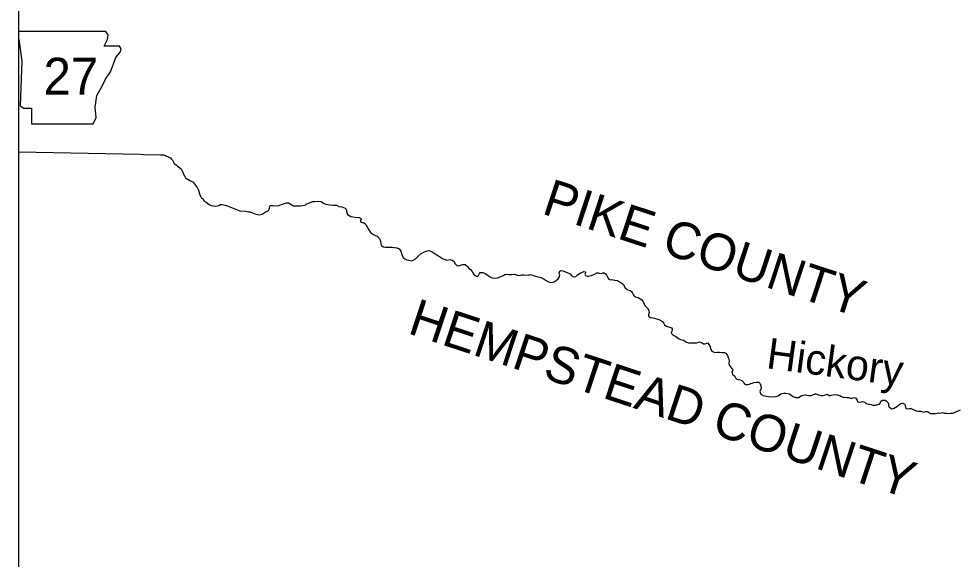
# Model space of a CAD drawing. Extents: x 79818 to 83933, y 50884 to 53307.
# Drawn here: x 80798.6 to 81014.4, y 52954.9 to 53079 of the extents above; entities that cross this region are included whole.
import ezdxf

# ---------------------------------------------------------------- set-up
doc = ezdxf.new("R2010")
doc.units = 0
for name, color, linetype in [('Level 2', 7, 'Continuous'), ('Level 21', 7, 'Continuous'), ('Level 30', 7, 'Continuous'), ('Level 9', 7, 'Continuous'), ('R_No Plot', 7, 'Continuous')]:
    doc.layers.add(name, color=color, linetype=linetype)

msp = doc.modelspace()

# ---------------------------------------------------------------- linework, layer by layer
at = {"layer": 'Level 2'}
for points in [[(80798.6, 53048.45), (80826.43, 53047.86), (80827.31, 53047.81), (80831.14, 53047.74)], [(80831.14, 53047.74), (80831.58, 53047.74), (80831.84, 53047.72), (80832.25, 53047.59), (80832.52, 53047.44), (80832.88, 53047.27), (80833.16, 53047.16), (80833.4, 53047.01), (80833.59, 53046.84), (80833.84, 53046.55), (80834.15, 53045.9), (80834.29, 53045.76), (80834.68, 53045.41), (80835.04, 53045.1), (80835.56, 53044.78), (80835.85, 53044.52), (80836.22, 53043.72), (80836.39, 53043.33), (80836.67, 53042.75), (80836.86, 53042.48), (80837.3, 53042.16), (80837.58, 53042.06), (80837.83, 53041.86), (80838.58, 53041.43), (80839.09, 53040.85), (80839.51, 53040.21), (80839.83, 53039.6), (80840.06, 53038.79), (80840.23, 53038.4), (80840.51, 53037.83), (80840.8, 53037.74), (80841.07, 53037.2), (80841.62, 53036.85), (80842.27, 53036.37), (80842.78, 53036.09), (80843.78, 53035.95), (80844.47, 53036.14), (80844.85, 53036.32), (80845.18, 53036.35), (80845.99, 53036.19), (80846.39, 53036.05), (80847.79, 53035.49), (80849.32, 53034.88), (80850.51, 53034.8), (80850.9, 53034.74), (80851.28, 53034.68), (80851.58, 53034.67), (80852.06, 53034.52), (80852.78, 53034.16), (80853.77, 53033.98), (80854.43, 53034.15), (80855.15, 53034.55), (80855.61, 53034.78), (80855.92, 53034.96), (80856.03, 53035.23), (80856.11, 53035.48), (80856.18, 53035.96), (80856.38, 53036.14), (80856.86, 53036.13), (80857.88, 53036.07), (80858.49, 53036.17), (80859.3, 53036.5), (80860.07, 53036.69), (80860.52, 53036.71), (80860.84, 53036.51), (80861.61, 53036.04), (80863.13, 53036), (80864.31, 53036.2), (80864.55, 53036.41), (80865.46, 53036.79), (80866.1, 53037), (80866.51, 53037.03), (80867.41, 53037.11), (80867.99, 53037.03), (80868.5, 53036.66), (80869.09, 53036.39), (80870, 53036.27), (80870.85, 53036.21), (80871.47, 53036.17), (80872.07, 53035.91), (80872.71, 53035.81), (80873.48, 53035.49), (80873.69, 53035.3), (80873.83, 53034.75), (80874.03, 53034.07), (80874.77, 53033.59), (80875.81, 53033.47), (80876.7, 53033.33), (80877, 53033.2), (80877.17, 53033.08), (80877.23, 53032.92), (80877.01, 53032.77), (80877.02, 53032.44), (80877.27, 53032.28), (80877.5, 53032.23), (80877.67, 53032.22), (80877.98, 53031.98), (80878.2, 53031.77)], [(80878.2, 53031.77), (80878.89, 53030.49), (80879.31, 53029.94), (80880, 53029.49), (80880.44, 53029.26), (80880.88, 53029.05), (80881, 53028.93), (80881.37, 53028.57), (80881.61, 53027.96), (80881.71, 53027.34), (80881.79, 53027.01), (80882.2, 53026.64), (80882.78, 53026.54), (80883.47, 53026.57), (80884.31, 53026.55), (80885.34, 53026.43), (80885.87, 53026.2), (80886.3, 53025.66), (80886.48, 53024.83), (80886.81, 53024.19), (80887.2, 53023.85), (80887.64, 53023.64), (80888.79, 53023.38), (80889.63, 53023.85), (80890.28, 53024.48), (80890.94, 53025.09), (80891.68, 53025.51), (80892.1, 53025.6), (80892.7, 53025.75), (80893.45, 53025.5), (80894.12, 53025.05), (80894.95, 53024.53), (80895.37, 53024.25), (80895.59, 53024.09), (80895.81, 53023.95), (80896.85, 53023.6), (80897.53, 53023.68), (80898.08, 53023.58), (80898.51, 53023.25), (80898.64, 53022.78), (80899.21, 53022.25), (80899.78, 53022.37), (80900.41, 53022.6), (80901.06, 53022.55), (80901.58, 53022.1), (80901.89, 53021.66), (80902.28, 53021.4), (80902.61, 53020.94), (80902.81, 53020.66), (80903.04, 53020.31), (80903.32, 53020.07), (80903.61, 53019.91), (80903.89, 53019.9), (80904.11, 53020.06), (80904.25, 53020.37), (80904.29, 53020.53), (80904.49, 53020.74), (80905.05, 53020.71), (80905.61, 53020.54), (80906.01, 53020.28), (80906.57, 53019.93), (80906.77, 53019.77), (80907.2, 53019.5), (80907.81, 53019.4), (80908.42, 53019.48), (80909.08, 53019.72), (80909.75, 53020.06), (80910.13, 53020.27), (80910.53, 53020.35), (80911.15, 53020.27), (80911.67, 53020.29), (80912.36, 53020.34), (80913.02, 53020.16), (80913.51, 53020.07), (80914, 53020.19), (80914.42, 53020.17), (80915.48, 53020.16), (80915.95, 53020.24), (80916.54, 53020.09), (80916.9, 53019.98), (80918, 53019.7), (80918.47, 53019.6), (80919.13, 53019.22), (80919.59, 53018.89), (80920.18, 53018.56), (80920.77, 53018.45), (80921.47, 53018.61), (80921.91, 53018.87), (80922.35, 53019.3), (80922.66, 53019.73), (80922.71, 53019.99), (80922.72, 53020.22), (80922.66, 53020.43), (80922.62, 53020.53), (80922.58, 53020.69), (80922.74, 53021.06), (80923.06, 53021.2), (80923.48, 53021.12), (80924.02, 53020.92), (80924.59, 53020.65), (80925.09, 53020.41)], [(80925.09, 53020.41), (80925.33, 53020.15), (80925.59, 53019.91), (80925.74, 53019.79), (80926.14, 53019.71), (80926.43, 53019.85), (80926.83, 53020.22), (80927.39, 53020.59), (80927.93, 53020.83), (80928.3, 53020.97), (80928.61, 53020.86), (80928.61, 53020.69), (80928.54, 53020.5), (80928.5, 53020.39), (80928.66, 53020.02), (80929.02, 53019.9), (80929.31, 53019.87), (80929.67, 53019.95), (80930.03, 53020.05), (80930.73, 53020.32), (80931.22, 53020.63), (80931.53, 53020.63), (80931.78, 53020.57), (80932.23, 53020.53), (80932.59, 53020.63), (80932.93, 53020.64), (80933.23, 53020.42), (80933.46, 53020.14), (80933.88, 53019.46), (80934, 53019.18), (80934.41, 53019.06), (80934.62, 53019.1), (80935.41, 53018.99), (80935.97, 53018.89), (80936.43, 53018.63), (80936.73, 53018.46), (80937.01, 53018.26), (80937.36, 53017.95), (80937.64, 53017.33), (80938.02, 53017.01), (80938.32, 53016.78), (80938.91, 53016.61), (80939.18, 53016.38), (80939.35, 53016.12), (80939.57, 53015.7), (80939.85, 53015.34), (80940.09, 53015.14), (80940.42, 53015.06), (80940.74, 53014.98), (80941.54, 53014.44), (80941.95, 53013.82), (80942.25, 53013.14), (80942.91, 53012.54), (80943.16, 53012.04), (80943.22, 53011.56), (80943.09, 53011.09), (80943.07, 53010.7), (80943.58, 53010.37), (80944.17, 53010.33), (80944.74, 53010.17), (80945.5, 53009.92), (80946.06, 53009.64), (80946.3, 53009.48), (80946.53, 53009.18), (80946.61, 53009.02), (80946.77, 53008.73), (80947.2, 53008.44), (80947.68, 53008.23), (80948.12, 53008.13), (80948.38, 53008.01), (80948.55, 53007.77), (80948.54, 53007.48), (80948.31, 53006.85), (80948.74, 53006.33), (80949.37, 53006.01), (80949.97, 53005.6), (80950.48, 53005.33), (80950.78, 53005.25), (80951.13, 53005.2), (80951.58, 53004.89), (80951.84, 53004.76), (80952.32, 53004.62), (80952.89, 53004.6), (80953.5, 53004.6), (80953.6, 53004.61), (80954.17, 53004.61), (80954.57, 53004.73), (80954.8, 53004.81), (80955.24, 53004.7), (80955.52, 53004.49), (80955.68, 53004.38), (80956.09, 53004.33), (80956.47, 53004.53), (80956.69, 53004.56), (80956.96, 53004.24), (80957.17, 53003.87), (80957.38, 53003.09), (80957.64, 53002.68), (80958.32, 53002.41), (80958.94, 53002.47), (80959.42, 53002.45)], [(80959.42, 53002.45), (80959.94, 53002.36), (80960.23, 53002.36), (80960.53, 53002.35), (80960.87, 53002.22), (80961.07, 53001.88), (80961.22, 53001.67), (80961.38, 53001.26), (80961.45, 53001.06), (80961.58, 53000.47), (80961.57, 52999.89), (80961.71, 52999.36), (80962.13, 52998.8), (80962.4, 52998.64), (80962.46, 52998.29), (80962.2, 52998.01), (80962.35, 52997.28), (80962.62, 52997.14), (80962.79, 52997.04), (80963.01, 52996.72), (80963.07, 52996.54), (80963.38, 52996.28), (80963.79, 52996.15), (80964.13, 52996.09), (80964.53, 52995.96), (80964.77, 52995.72), (80964.98, 52995.49), (80965.08, 52995.24), (80965.42, 52995.01), (80965.88, 52995), (80966.25, 52995.11), (80966.62, 52995.26), (80966.86, 52995.36), (80967.24, 52995.5), (80967.78, 52995.57), (80968.17, 52995.58), (80968.45, 52995.54), (80968.68, 52995.33), (80968.73, 52995.22), (80968.85, 52994.81), (80968.87, 52994.61), (80968.93, 52994.37), (80968.95, 52994.09), (80968.8, 52993.78), (80968.67, 52993.4), (80968.78, 52992.94), (80968.88, 52992.79), (80969.38, 52992.48), (80970.15, 52992.34), (80970.58, 52992.25), (80971.46, 52992.22), (80972.25, 52992.25), (80972.86, 52992.46), (80973.5, 52992.89), (80974.18, 52993.06), (80974.59, 52993.04), (80975.47, 52992.86), (80975.95, 52992.54), (80976.33, 52992.29), (80976.85, 52992.07), (80977.49, 52992.02), (80978.31, 52992.53), (80979.01, 52992.69), (80979.17, 52992.67), (80979.9, 52992.51), (80980.41, 52992.52), (80981.33, 52992.86), (80981.49, 52992.91), (80981.9, 52992.75), (80982.14, 52992.67), (80982.74, 52992.53), (80983.22, 52992.5), (80983.72, 52992.65), (80984.04, 52992.78), (80984.34, 52992.68), (80984.6, 52992.54), (80984.85, 52992.5), (80985.06, 52992.6), (80985.73, 52992.71), (80986.49, 52992.63), (80986.72, 52992.58), (80987.01, 52992.48), (80987.4, 52992.28), (80987.68, 52992.1), (80988.01, 52992.15), (80988.71, 52992.07), (80989.05, 52992.02), (80989.47, 52991.91), (80989.87, 52991.91), (80990.21, 52992.02), (80990.67, 52991.86), (80990.84, 52991.65), (80990.96, 52991.42), (80991.1, 52991.08), (80991.4, 52990.98), (80991.9, 52991.08), (80992.2, 52991.13), (80992.74, 52991.01), (80993.06, 52990.69), (80993.62, 52990.53), (80993.84, 52990.51)], [(80993.84, 52990.51), (80994.2, 52990.42), (80994.55, 52990.31), (80994.78, 52990.26), (80995.11, 52990.28), (80995.27, 52990.3), (80995.75, 52990.42), (80996.12, 52990.51), (80996.32, 52990.85), (80996.32, 52991.01), (80996.42, 52991.22), (80996.79, 52991.41), (80997.03, 52991.44), (80997.39, 52991.41), (80997.71, 52991.24), (80998.11, 52990.86), (80998.19, 52990.61), (80998.21, 52990.24), (80998.26, 52989.98), (80998.86, 52989.44), (80999.36, 52989.5), (81000.25, 52990.09), (81000.58, 52990.39), (81000.77, 52990.55), (81001.03, 52990.71), (81001.29, 52990.78), (81001.46, 52990.73), (81001.79, 52990.57), (81001.95, 52990.42), (81002.03, 52990.17), (81002.1, 52989.87), (81002.17, 52989.55), (81002.53, 52989.42), (81002.9, 52989.54), (81003.32, 52989.55), (81003.88, 52989.27), (81004.36, 52989.1), (81004.56, 52989.02), (81005.02, 52988.94), (81005.36, 52988.9), (81005.59, 52988.93), (81005.81, 52988.82), (81006.32, 52988.72), (81006.67, 52988.83), (81006.87, 52988.87), (81007.13, 52988.83), (81007.33, 52988.68), (81007.57, 52988.51), (81007.83, 52988.41), (81008.25, 52988.39), (81008.96, 52988.39), (81009.39, 52988.49), (81009.63, 52988.53), (81010.04, 52988.46), (81010.55, 52988.57), (81011.04, 52988.48), (81011.49, 52988.44), (81012.08, 52988.41), (81012.42, 52988.47), (81012.91, 52988.45), (81013.47, 52988.65), (81014.29, 52989.06), (81014.68, 52989.22)]]:
    msp.add_lwpolyline(points, dxfattribs=at)
at = {"layer": 'Level 21'}
msp.add_lwpolyline([(80798.6, 53074.17), (80799.33, 53069.27), (80798.88, 53059.01), (80799.79, 53058.44), (80801.48, 53058.44), (80801.48, 53054.83), (80815.69, 53054.83), (80816.37, 53056.3), (80816.14, 53058.67), (80816.48, 53061.37), (80817.72, 53063.52), (80818.51, 53065.1), (80819.64, 53066.79), (80820.31, 53068.59), (80820.88, 53070.06), (80821.89, 53071.3), (80822.12, 53072.09), (80821.67, 53072.65), (80818.17, 53072.65), (80818.96, 53074.23), (80819.07, 53075.25), (80818.6, 53076.03), (80798.6, 53076.04)], dxfattribs=at)
at = {"layer": 'R_No Plot'}
msp.add_lwpolyline([(80798.6, 53193.52), (81459.98, 53193.52), (81459.98, 52610.7), (80798.6, 52610.7)], close=True, dxfattribs=at)
msp.add_lwpolyline([(80798.6, 53193.52), (81459.98, 53193.52), (81459.98, 52610.7), (80798.6, 52610.7)], close=True, dxfattribs=at)

# ---------------------------------------------------------------- texts
at = {"layer": 'Level 21'}
msp.add_text('27', height=8.448, dxfattribs=at).set_placement((80804.27, 53061.57))
at = {"layer": 'Level 30'}
for s, rotation, p in [('PIKE COUNTY', 341.8428, (80918.36, 53034.32)), ('HEMPSTEAD COUNTY', 341.6896, (80887.58, 53006.86))]:
    msp.add_text(s, height=8.448, rotation=rotation, dxfattribs=at).set_placement(p)
at = {"layer": 'Level 9'}
msp.add_text('Hickory', height=7.04, rotation=352.3423, dxfattribs=at).set_placement((80969.94, 52998.81))

doc.saveas('drawing.dxf')
